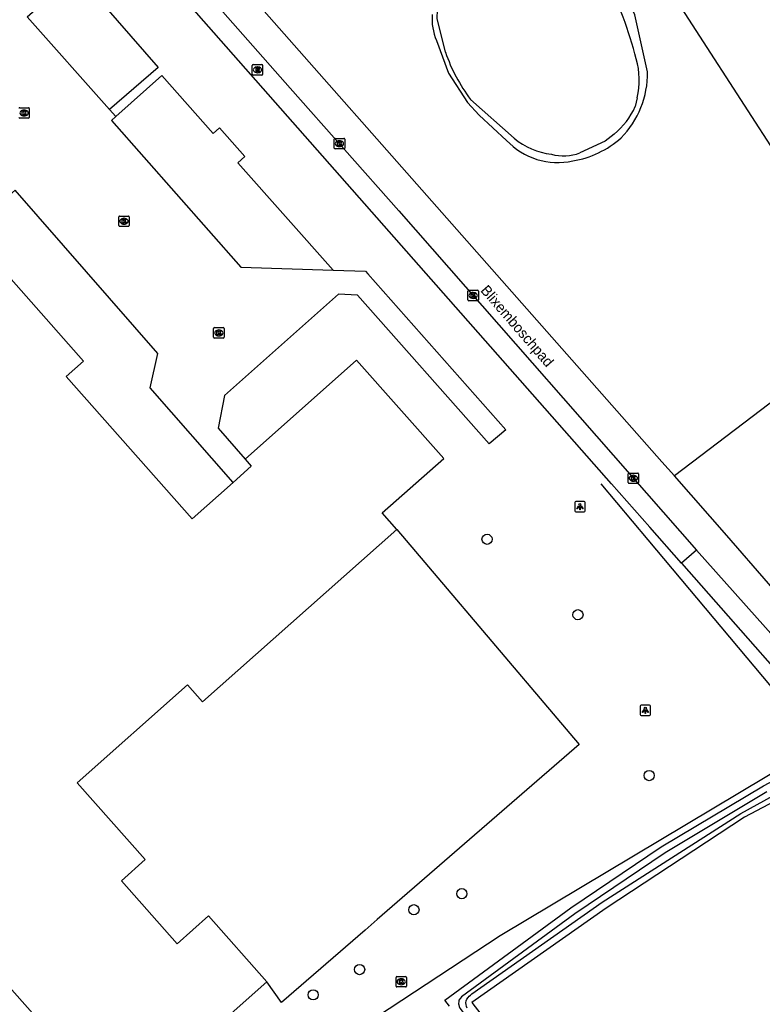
# Model space of a CAD drawing. Extents: x 159451 to 160663, y 388402 to 389723.
# Drawn here: x 159842 to 159913.3, y 389010.8 to 389105.4 of the extents above; entities that cross this region are included whole.
import ezdxf

# ---------------------------------------------------------------- set-up
doc = ezdxf.new("R2010")
doc.units = 0
for name, color, linetype in [('IMGEO_Berm_groen', 7, 'Continuous'), ('IMGEO_Boom', 7, 'Continuous'), ('IMGEO_Fietspad_gesloten', 7, 'Continuous'), ('IMGEO_Greppel_droge_sloot', 7, 'Continuous'), ('IMGEO_Groenvoorziening', 7, 'Continuous'), ('IMGEO_Haag', 7, 'Continuous'), ('IMGEO_Hek', 7, 'Continuous'), ('IMGEO_Kolk', 7, 'Continuous'), ('IMGEO_Lichtpunt', 7, 'Continuous'), ('IMGEO_Loofbos', 7, 'Continuous'), ('IMGEO_Meer_plas_ven_vijver', 7, 'Continuous'), ('IMGEO_Openbare_ruimte_label', 7, 'Continuous'), ('IMGEO_Pand', 7, 'Continuous'), ('IMGEO_Rioolput', 7, 'Continuous'), ('IMGEO_Voetpad_open', 7, 'Continuous')]:
    doc.layers.add(name, color=color, linetype=linetype)

msp = doc.modelspace()

# ---------------------------------------------------------------- linework, layer by layer
at = {"layer": 'IMGEO_Berm_groen'}
msp.add_lwpolyline([(159905.576, 389053.15), (159920.927, 389035.738)], dxfattribs=at)
at = {"layer": 'IMGEO_Boom'}
for centre in [(159886.897, 389055.455), (159895.63, 389048.207), (159902.477, 389032.747), (159884.474, 389021.4), (159879.868, 389019.859), (159874.648, 389014.107), (159870.188, 389011.676)]:
    msp.add_circle(centre, 0.489, dxfattribs=at)
at = {"layer": 'IMGEO_Fietspad_gesloten'}
for points in [[(159904.895, 389061.543), (159903.701, 389062.897), (159844.345, 389130.192), (159838.071, 389138.004), (159828.517, 389151.959), (159799.274, 389200.071), (159799.396, 389200.15)], [(159796.892, 389198.348), (159802.378, 389189.41), (159812.113, 389173.259), (159824.51, 389152.818), (159827.921, 389147.595), (159831.086, 389142.869), (159835.508, 389136.478), (159838.565, 389132.611), (159846.191, 389123.514), (159867.979, 389098.815), (159878.426, 389087.019), (159907.007, 389054.412)], [(159926.138, 389036.407), (159917.946, 389046.597), (159909.939, 389055.824), (159904.895, 389061.543)], [(159907.007, 389054.412), (159915.504, 389044.884), (159924.271, 389033.99)]]:
    msp.add_lwpolyline(points, dxfattribs=at)
at = {"layer": 'IMGEO_Greppel_droge_sloot'}
for points in [[(159884.98, 389010.408), (159884.923, 389010.575), (159884.875, 389010.761), (159884.859, 389010.926), (159884.881, 389011.102), (159884.956, 389011.261), (159885.069, 389011.409), (159885.185, 389011.537), (159885.311, 389011.661), (159885.439, 389011.782), (159897.967, 389020.574), (159911.294, 389029.097), (159920.691, 389034.302)], [(159913.791, 389031.179), (159903.996, 389025.321), (159895.332, 389019.468), (159884.451, 389011.488), (159884.332, 389011.361), (159884.199, 389011.16), (159884.168, 389011.066), (159884.153, 389010.81), (159884.169, 389010.724), (159884.22, 389010.561), (159884.288, 389010.402), (159910.131, 388976.782), (159910.558, 388976.229), (159911.479, 388975.035), (159911.878, 388974.519), (159911.873, 388974.516), (159918.111, 388966.007)]]:
    msp.add_lwpolyline(points, dxfattribs=at)
at = {"layer": 'IMGEO_Groenvoorziening'}
for points in [[(159845.947, 389108.495), (159847.419, 389109.857), (159855.3, 389100.798), (159850.616, 389096.745)], [(159878.226, 389056.393), (159883.974, 389049.649), (159885.198, 389048.172), (159895.746, 389035.738), (159876.34, 389018.905), (159875.178, 389017.897), (159867.152, 389010.935), (159865.746, 389012.934)], [(159883.272, 389010.605), (159882.848, 389011.158), (159894.939, 389020.026), (159903.63, 389025.897), (159913.456, 389031.773), (159920.927, 389035.738)]]:
    msp.add_lwpolyline(points, dxfattribs=at)
at = {"layer": 'IMGEO_Haag'}
for points in [[(159902.323, 389100.361), (159901.113, 389105.86), (159898.558, 389111.512), (159891.029, 389124.867), (159885.405, 389133.486)], [(159882.025, 389103.387), (159883.194, 389100.251), (159885.024, 389097.424), (159886.14, 389096.194), (159888.763, 389093.782)]]:
    msp.add_lwpolyline(points, dxfattribs=at)
for centre, radius, start, end in [((159886.844, 389105.427), 5.233, 174.98856, 202.94491), ((159893.378, 389100.268), 8.945, 315.64181, 0.59671), ((159893.708, 389098.472), 6.815, 223.47876, 282.11635), ((159893.575, 389101.066), 9.389, 279.58726, 311.3164)]:
    msp.add_arc(centre, radius, start, end, dxfattribs=at)
at = {"layer": 'IMGEO_Hek'}
for points in [[(159897.842, 389060.789), (159902.352, 389055.414)], [(159902.352, 389055.414), (159918.877, 389035.717), (159888.157, 389017.355), (159875.155, 389008.783), (159870.782, 389006.704), (159868.88, 389005.219), (159856.442, 388994.83)]]:
    msp.add_lwpolyline(points, dxfattribs=at)
at = {"layer": 'IMGEO_Kolk'}
for p, q in [((159841.984, 389096.918), (159842.836, 389096.918)), ((159842.397, 389096.698), (159842.422, 389096.698)), ((159842.91, 389096.844), (159842.91, 389095.992)), ((159842.836, 389095.918), (159841.984, 389095.918)), ((159842.42, 389096.138), (159842.395, 389096.138)), ((159872.213, 389093.045), (159872.213, 389093.897)), ((159872.288, 389093.971), (159873.14, 389093.971)), ((159872.701, 389093.751), (159872.726, 389093.751)), ((159873.214, 389093.897), (159873.214, 389093.045)), ((159873.14, 389092.971), (159872.288, 389092.971)), ((159872.724, 389093.191), (159872.699, 389093.191)), ((159851.507, 389085.59), (159851.507, 389086.442)), ((159851.582, 389086.516), (159852.434, 389086.516)), ((159851.995, 389086.296), (159852.02, 389086.296)), ((159852.508, 389086.442), (159852.508, 389085.59)), ((159852.434, 389085.516), (159851.582, 389085.516)), ((159852.018, 389085.736), (159851.993, 389085.736)), ((159885.06, 389078.455), (159885.06, 389079.307)), ((159885.135, 389079.381), (159885.987, 389079.381)), ((159886.061, 389079.307), (159886.061, 389078.455)), ((159885.987, 389078.381), (159885.135, 389078.381)), ((159885.571, 389078.601), (159885.546, 389078.601)), ((159885.548, 389079.161), (159885.573, 389079.161)), ((159860.623, 389074.862), (159860.623, 389075.714)), ((159860.698, 389075.788), (159861.55, 389075.788)), ((159861.111, 389075.568), (159861.136, 389075.568)), ((159861.624, 389075.714), (159861.624, 389074.862)), ((159861.55, 389074.788), (159860.698, 389074.788)), ((159861.134, 389075.008), (159861.109, 389075.008)), ((159900.452, 389060.895), (159900.452, 389061.747)), ((159900.527, 389061.821), (159901.379, 389061.821)), ((159900.94, 389061.601), (159900.965, 389061.601)), ((159901.453, 389061.747), (159901.453, 389060.895)), ((159901.379, 389060.821), (159900.527, 389060.821)), ((159900.963, 389061.041), (159900.938, 389061.041)), ((159878.147, 389012.509), (159878.147, 389013.361)), ((159878.222, 389013.435), (159879.074, 389013.435)), ((159878.635, 389013.215), (159878.66, 389013.215)), ((159879.148, 389013.361), (159879.148, 389012.509)), ((159879.074, 389012.435), (159878.222, 389012.435)), ((159878.658, 389012.655), (159878.633, 389012.655))]:
    msp.add_line(p, q, dxfattribs=at)
for points in [[(159841.984, 389096.918), (159842.836, 389096.918)], [(159842.23, 389096.618), (159842.353, 389096.618), (159842.353, 389096.467), (159842.483, 389096.618), (159842.647, 389096.618), (159842.501, 389096.467), (159842.654, 389096.218), (159842.502, 389096.218), (159842.417, 389096.382), (159842.353, 389096.315), (159842.353, 389096.218), (159842.23, 389096.218), (159842.23, 389096.618)], [(159842.91, 389096.844), (159842.91, 389095.992)], [(159842.836, 389095.918), (159841.984, 389095.918)], [(159872.213, 389093.045), (159872.213, 389093.897)], [(159872.288, 389093.971), (159873.14, 389093.971)], [(159872.534, 389093.671), (159872.657, 389093.671), (159872.657, 389093.52), (159872.787, 389093.671), (159872.951, 389093.671), (159872.805, 389093.52), (159872.958, 389093.271), (159872.806, 389093.271), (159872.721, 389093.435), (159872.657, 389093.368), (159872.657, 389093.271), (159872.534, 389093.271), (159872.534, 389093.671)], [(159873.214, 389093.897), (159873.214, 389093.045)], [(159873.14, 389092.971), (159872.288, 389092.971)], [(159851.507, 389085.59), (159851.507, 389086.442)], [(159851.582, 389086.516), (159852.434, 389086.516)], [(159851.828, 389086.216), (159851.951, 389086.216), (159851.951, 389086.065), (159852.081, 389086.216), (159852.245, 389086.216), (159852.099, 389086.065), (159852.252, 389085.816), (159852.1, 389085.816), (159852.015, 389085.98), (159851.951, 389085.913), (159851.951, 389085.816), (159851.828, 389085.816), (159851.828, 389086.216)], [(159852.508, 389086.442), (159852.508, 389085.59)], [(159852.434, 389085.516), (159851.582, 389085.516)], [(159885.06, 389078.455), (159885.06, 389079.307)], [(159885.135, 389079.381), (159885.987, 389079.381)], [(159886.061, 389079.307), (159886.061, 389078.455)], [(159885.987, 389078.381), (159885.135, 389078.381)], [(159885.381, 389079.081), (159885.504, 389079.081), (159885.504, 389078.93), (159885.634, 389079.081), (159885.798, 389079.081), (159885.652, 389078.93), (159885.805, 389078.681), (159885.653, 389078.681), (159885.568, 389078.845), (159885.504, 389078.778), (159885.504, 389078.681), (159885.381, 389078.681), (159885.381, 389079.081)], [(159860.623, 389074.862), (159860.623, 389075.714)], [(159860.698, 389075.788), (159861.55, 389075.788)], [(159860.944, 389075.488), (159861.067, 389075.488), (159861.067, 389075.337), (159861.197, 389075.488), (159861.361, 389075.488), (159861.215, 389075.337), (159861.368, 389075.088), (159861.216, 389075.088), (159861.131, 389075.252), (159861.067, 389075.185), (159861.067, 389075.088), (159860.944, 389075.088), (159860.944, 389075.488)], [(159861.624, 389075.714), (159861.624, 389074.862)], [(159861.55, 389074.788), (159860.698, 389074.788)], [(159900.452, 389060.895), (159900.452, 389061.747)], [(159900.527, 389061.821), (159901.379, 389061.821)], [(159900.773, 389061.521), (159900.896, 389061.521), (159900.896, 389061.37), (159901.026, 389061.521), (159901.19, 389061.521), (159901.044, 389061.37), (159901.197, 389061.121), (159901.045, 389061.121), (159900.96, 389061.285), (159900.896, 389061.218), (159900.896, 389061.121), (159900.773, 389061.121), (159900.773, 389061.521)], [(159901.453, 389061.747), (159901.453, 389060.895)], [(159901.379, 389060.821), (159900.527, 389060.821)], [(159878.147, 389012.509), (159878.147, 389013.361)], [(159878.222, 389013.435), (159879.074, 389013.435)], [(159878.468, 389013.135), (159878.591, 389013.135), (159878.591, 389012.984), (159878.721, 389013.135), (159878.885, 389013.135), (159878.739, 389012.984), (159878.892, 389012.735), (159878.74, 389012.735), (159878.655, 389012.899), (159878.591, 389012.832), (159878.591, 389012.735), (159878.468, 389012.735), (159878.468, 389013.135)], [(159879.148, 389013.361), (159879.148, 389012.509)], [(159879.074, 389012.435), (159878.222, 389012.435)]]:
    msp.add_lwpolyline(points, dxfattribs=at)
for centre, start, end in [((159841.986, 389096.842), 91.55205, 178.44795), ((159841.986, 389096.842), 91.55205, 178.44795), ((159842.834, 389096.842), 1.55205, 88.44795), ((159842.834, 389096.842), 1.55205, 88.44795), ((159841.986, 389095.994), 181.55205, 268.44795), ((159841.986, 389095.994), 181.55205, 268.44795), ((159842.834, 389095.994), 271.55205, 358.44795), ((159842.834, 389095.994), 271.55205, 358.44795), ((159872.29, 389093.895), 91.55205, 178.44795), ((159872.29, 389093.895), 91.55205, 178.44795), ((159873.138, 389093.895), 1.55205, 88.44795), ((159873.138, 389093.895), 1.55205, 88.44795), ((159872.29, 389093.047), 181.55205, 268.44795), ((159872.29, 389093.047), 181.55205, 268.44795), ((159873.138, 389093.047), 271.55205, 358.44795), ((159873.138, 389093.047), 271.55205, 358.44795), ((159851.584, 389086.44), 91.55205, 178.44795), ((159851.584, 389086.44), 91.55205, 178.44795), ((159852.432, 389086.44), 1.55205, 88.44795), ((159852.432, 389086.44), 1.55205, 88.44795), ((159851.584, 389085.592), 181.55205, 268.44795), ((159851.584, 389085.592), 181.55205, 268.44795), ((159852.432, 389085.592), 271.55205, 358.44795), ((159852.432, 389085.592), 271.55205, 358.44795), ((159885.137, 389079.305), 91.55205, 178.44795), ((159885.137, 389079.305), 91.55205, 178.44795), ((159885.985, 389079.305), 1.55205, 88.44795), ((159885.985, 389079.305), 1.55205, 88.44795), ((159885.137, 389078.457), 181.55205, 268.44795), ((159885.137, 389078.457), 181.55205, 268.44795), ((159885.985, 389078.457), 271.55205, 358.44795), ((159885.985, 389078.457), 271.55205, 358.44795), ((159860.7, 389075.712), 91.55205, 178.44795), ((159860.7, 389075.712), 91.55205, 178.44795), ((159861.548, 389075.712), 1.55205, 88.44795), ((159861.548, 389075.712), 1.55205, 88.44795), ((159860.7, 389074.864), 181.55205, 268.44795), ((159860.7, 389074.864), 181.55205, 268.44795), ((159861.548, 389074.864), 271.55205, 358.44795), ((159861.548, 389074.864), 271.55205, 358.44795), ((159900.529, 389061.745), 91.55205, 178.44795), ((159900.529, 389061.745), 91.55205, 178.44795), ((159901.377, 389061.745), 1.55205, 88.44795), ((159901.377, 389061.745), 1.55205, 88.44795), ((159900.529, 389060.897), 181.55205, 268.44795), ((159900.529, 389060.897), 181.55205, 268.44795), ((159901.377, 389060.897), 271.55205, 358.44795), ((159901.377, 389060.897), 271.55205, 358.44795), ((159878.224, 389013.359), 91.55205, 178.44795), ((159878.224, 389013.359), 91.55205, 178.44795), ((159879.072, 389013.359), 1.55205, 88.44795), ((159879.072, 389013.359), 1.55205, 88.44795), ((159878.224, 389012.511), 181.55205, 268.44795), ((159878.224, 389012.511), 181.55205, 268.44795), ((159879.072, 389012.511), 271.55205, 358.44795), ((159879.072, 389012.511), 271.55205, 358.44795)]:
    msp.add_arc(centre, 0.0765, start, end, dxfattribs=at)
for centre, major_axis, ratio, start_param, end_param in [((159842.396, 389096.418), (-0.387, 0.002), 0.722429, 4.712389, 7.853982), ((159842.421, 389096.418), (-0.39, 0.002), 0.717154, 1.570796, 4.712389), ((159872.7, 389093.471), (-0.387, 0.002), 0.722429, 4.712389, 7.853982), ((159872.725, 389093.471), (-0.39, 0.002), 0.717154, 1.570796, 4.712389), ((159851.994, 389086.016), (-0.387, 0.002), 0.722429, 4.712389, 7.853982), ((159852.019, 389086.016), (-0.39, 0.002), 0.717154, 1.570796, 4.712389), ((159885.547, 389078.881), (-0.387, 0.002), 0.722429, 4.712389, 7.853982), ((159885.572, 389078.881), (-0.39, 0.002), 0.717154, 1.570796, 4.712389), ((159861.11, 389075.288), (-0.387, 0.002), 0.722429, 4.712389, 7.853982), ((159861.135, 389075.288), (-0.39, 0.002), 0.717154, 1.570796, 4.712389), ((159900.939, 389061.321), (-0.387, 0.002), 0.722429, 4.712389, 7.853982), ((159900.964, 389061.321), (-0.39, 0.002), 0.717154, 1.570796, 4.712389), ((159878.634, 389012.935), (-0.387, 0.002), 0.722429, 4.712389, 7.853982), ((159878.659, 389012.935), (-0.39, 0.002), 0.717154, 1.570796, 4.712389)]:
    msp.add_ellipse(centre, major_axis=major_axis, ratio=ratio, start_param=start_param, end_param=end_param, dxfattribs=at)
at = {"layer": 'IMGEO_Lichtpunt'}
for p, q in [((159895.321, 389058.994), (159895.321, 389058.187)), ((159895.321, 389058.994), (159895.321, 389058.187)), ((159896.223, 389059.089), (159895.415, 389059.089)), ((159896.223, 389059.089), (159895.415, 389059.089)), ((159896.317, 389058.187), (159896.317, 389058.994)), ((159896.317, 389058.187), (159896.317, 389058.994)), ((159895.415, 389058.093), (159896.223, 389058.093)), ((159895.415, 389058.093), (159896.223, 389058.093)), ((159902.508, 389039.519), (159901.7, 389039.519)), ((159902.508, 389039.519), (159901.7, 389039.519)), ((159901.606, 389039.424), (159901.606, 389038.617)), ((159901.606, 389039.424), (159901.606, 389038.617)), ((159902.602, 389038.617), (159902.602, 389039.424)), ((159902.602, 389038.617), (159902.602, 389039.424)), ((159901.7, 389038.523), (159902.508, 389038.523)), ((159901.7, 389038.523), (159902.508, 389038.523))]:
    msp.add_line(p, q, dxfattribs=at)
for points in [[(159895.695, 389058.658), (159895.734, 389058.63), (159895.546, 389058.368), (159895.508, 389058.395), (159895.695, 389058.658)], [(159895.797, 389058.61), (159895.844, 389058.61), (159895.844, 389058.288), (159895.797, 389058.288), (159895.797, 389058.61)], [(159895.907, 389058.63), (159895.945, 389058.657), (159896.132, 389058.395), (159896.093, 389058.367), (159895.907, 389058.63)], [(159901.98, 389039.088), (159902.019, 389039.06), (159901.831, 389038.798), (159901.793, 389038.825), (159901.98, 389039.088)], [(159902.082, 389039.04), (159902.129, 389039.04), (159902.129, 389038.718), (159902.082, 389038.718), (159902.082, 389039.04)], [(159902.192, 389039.06), (159902.23, 389039.087), (159902.417, 389038.825), (159902.378, 389038.797), (159902.192, 389039.06)]]:
    msp.add_lwpolyline(points, dxfattribs=at)
for centre in [(159895.82, 389058.792), (159902.105, 389039.222)]:
    msp.add_circle(centre, 0.0994, dxfattribs=at)
for centre, start, end in [((159895.415, 389058.994), 90, 180), ((159895.415, 389058.994), 90, 180), ((159896.223, 389058.994), 0, 90), ((159896.223, 389058.994), 0, 90), ((159895.415, 389058.187), 180, 270), ((159895.415, 389058.187), 180, 270), ((159896.223, 389058.187), 270, 0), ((159896.223, 389058.187), 270, 360), ((159901.7, 389039.424), 90, 180), ((159901.7, 389039.424), 90, 180), ((159902.508, 389039.424), 0, 90), ((159902.508, 389039.424), 0, 90), ((159901.7, 389038.617), 180, 270), ((159901.7, 389038.617), 180, 270), ((159902.508, 389038.617), 270, 0), ((159902.508, 389038.617), 270, 360)]:
    msp.add_arc(centre, 0.0946, start, end, dxfattribs=at)
at = {"layer": 'IMGEO_Loofbos'}
for points in [[(159920.651, 389073.487), (159904.895, 389061.543)], [(159922.016, 389034.23), (159911.641, 389028.75), (159898.35, 389020.01), (159885.43, 389010.942), (159919.2, 388967.183), (159936.657, 388977.126), (159947.412, 388982.612), (159956.503, 388986.851), (159956.108, 388989.074), (159925.88, 389027.51)]]:
    msp.add_lwpolyline(points, dxfattribs=at)
at = {"layer": 'IMGEO_Meer_plas_ven_vijver'}
for points in [[(159882.901, 389102.258), (159882.087, 389105.496), (159882.151, 389107.151)], [(159889.5, 389093.989), (159885.307, 389097.723)], [(159901.334, 389097.887), (159901.138, 389097.042)], [(159899.116, 389094.374), (159898.24, 389093.717), (159895.822, 389092.572)]]:
    msp.add_lwpolyline(points, dxfattribs=at)
for centre, radius, start, end in [((159864.345, 389092.181), 38.075, 14.32893, 26.97191), ((159898.201, 389107.47), 16.164, 198.81018, 217.08532), ((159894.117, 389099.557), 7.408, 346.97535, 16.0452), ((159894.497, 389099.975), 7.259, 309.51194, 336.17319), ((159893.995, 389099.49), 7.104, 230.74579, 262.55168), ((159894.236, 389097.129), 4.825, 256.06223, 289.18829)]:
    msp.add_arc(centre, radius, start, end, dxfattribs=at)
at = {"layer": 'IMGEO_Pand'}
for points in [[(159915.235, 389091.624), (159899.45, 389116.005), (159900.096, 389116.423), (159898.241, 389119.28), (159897.523, 389118.816), (159885.948, 389136.668), (159891.126, 389140.025), (159886.437, 389147.258), (159884.283, 389145.833), (159877.553, 389156.211), (159881.723, 389158.916), (159880.624, 389160.611), (159879.608, 389159.976), (159876.066, 389160.72), (159874.084, 389163.771), (159874.836, 389167.333), (159877.877, 389169.32), (159881.445, 389168.547)], [(159862.491, 389060.918), (159858.562, 389057.434), (159846.456, 389071.083), (159848.122, 389072.56), (159837.049, 389085.046)], [(159878.226, 389056.393), (159876.818, 389057.981), (159882.727, 389063.221), (159874.361, 389072.656), (159863.642, 389063.15)], [(159863.642, 389063.15), (159864.243, 389062.472), (159862.491, 389060.918)], [(159865.746, 389012.934), (159860.137, 389019.258), (159857.121, 389016.583), (159851.756, 389022.633), (159854.053, 389024.67), (159847.5, 389032.058), (159858.111, 389041.468), (159859.558, 389039.837), (159878.226, 389056.393)], [(159783.5, 388991.925), (159786.565, 388987.974), (159798.702, 388997.387), (159802.753, 388992.163), (159815.387, 389001.916), (159796.196, 389026.186), (159795.492, 389025.64), (159793.911, 389027.679), (159803.651, 389035.504), (159803.357, 389035.87), (159806.087, 389038.111), (159807.904, 389035.943), (159818.496, 389045.311), (159819.106, 389044.622), (159819.353, 389044.841), (159830.839, 389031.891), (159826.85, 389028.353), (159851.628, 389000.413)], [(159851.628, 389000.413), (159865.746, 389012.934)]]:
    msp.add_lwpolyline(points, dxfattribs=at)
at = {"layer": 'IMGEO_Rioolput'}
for p, q in [((159864.332, 389100.138), (159864.332, 389100.99)), ((159864.407, 389101.064), (159865.259, 389101.064)), ((159865.333, 389100.99), (159865.333, 389100.138)), ((159865.259, 389100.064), (159864.407, 389100.064)), ((159864.843, 389100.284), (159864.818, 389100.284)), ((159864.82, 389100.844), (159864.845, 389100.844))]:
    msp.add_line(p, q, dxfattribs=at)
for points in [[(159864.332, 389100.138), (159864.332, 389100.99)], [(159864.407, 389101.064), (159865.259, 389101.064)], [(159865.333, 389100.99), (159865.333, 389100.138)], [(159865.259, 389100.064), (159864.407, 389100.064)], [(159864.921, 389100.762), (159864.669, 389100.764), (159864.669, 389100.364)], [(159864.669, 389100.364), (159864.793, 389100.364), (159864.793, 389100.526), (159864.804, 389100.526)], [(159864.847, 389100.683), (159864.793, 389100.683), (159864.793, 389100.602)], [(159864.793, 389100.602), (159864.845, 389100.602)], [(159864.851, 389100.497), (159864.922, 389100.364), (159865.062, 389100.364), (159864.997, 389100.49)]]:
    msp.add_lwpolyline(points, dxfattribs=at)
for centre, radius, start, end in [((159864.409, 389100.988), 0.0765, 91.55205, 178.44795), ((159864.409, 389100.988), 0.0765, 91.55205, 178.44795), ((159865.257, 389100.988), 0.0765, 1.55205, 88.44795), ((159865.257, 389100.988), 0.0765, 1.55205, 88.44795), ((159864.409, 389100.14), 0.0765, 181.55205, 268.44795), ((159864.409, 389100.14), 0.0765, 181.55205, 268.44795), ((159864.803, 389100.473), 0.0533, 26.02933, 88.69889), ((159864.829, 389100.791), 0.19, 274.7715, 282.96867), ((159864.853, 389100.587), 0.0964, 77.00612, 93.18647), ((159864.867, 389100.644), 0.0378, 276.66336, 79.67722), ((159864.92, 389100.652), 0.109, 350.36119, 89.41601), ((159864.918, 389100.652), 0.112, 277.58423, 350.98172), ((159864.902, 389100.437), 0.108, 29.51342, 73.79051), ((159865.257, 389100.14), 0.0765, 271.55205, 358.44795), ((159865.257, 389100.14), 0.0765, 271.55205, 358.44795)]:
    msp.add_arc(centre, radius, start, end, dxfattribs=at)
for centre, major_axis, ratio, start_param, end_param in [((159864.819, 389100.564), (-0.387, 0.002), 0.722429, 4.712389, 7.853982), ((159864.844, 389100.564), (-0.39, 0.002), 0.717154, 1.570796, 4.712389)]:
    msp.add_ellipse(centre, major_axis=major_axis, ratio=ratio, start_param=start_param, end_param=end_param, dxfattribs=at)
at = {"layer": 'IMGEO_Voetpad_open'}
for points in [[(159905.576, 389053.15), (159902.525, 389056.603), (159898.84, 389060.773), (159850.911, 389115.222)], [(159850.616, 389096.745), (159842.698, 389105.67), (159845.947, 389108.495)], [(159872.106, 389081.321), (159862.951, 389091.642), (159863.626, 389092.24), (159861.183, 389094.994), (159860.575, 389094.455), (159855.654, 389100.003), (159851.217, 389096.067)], [(159850.616, 389096.745), (159851.217, 389096.067)], [(159851.217, 389096.067), (159850.809, 389095.705), (159863.225, 389081.615), (159872.106, 389081.321)], [(159862.491, 389060.918), (159854.515, 389070.02), (159855.247, 389073.32), (159841.539, 389088.988), (159837.049, 389085.046)], [(159872.106, 389081.321), (159875.228, 389081.217), (159875.441, 389080.976), (159888.715, 389065.964), (159887.086, 389064.638), (159874.447, 389078.895), (159872.627, 389079.011), (159861.654, 389069.275), (159861.062, 389066.135), (159863.642, 389063.15)], [(159907.007, 389054.412), (159905.576, 389053.15)]]:
    msp.add_lwpolyline(points, dxfattribs=at)

# ---------------------------------------------------------------- texts
at = {"layer": 'IMGEO_Openbare_ruimte_label'}
msp.add_text('Blixemboschpad', height=1, rotation=310.86241, dxfattribs=at).set_placement((159886.211, 389079.334))

doc.saveas('drawing.dxf')
